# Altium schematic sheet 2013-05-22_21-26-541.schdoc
size 384 x 220 mm; SheetNumber: 1; SheetTotal: 1
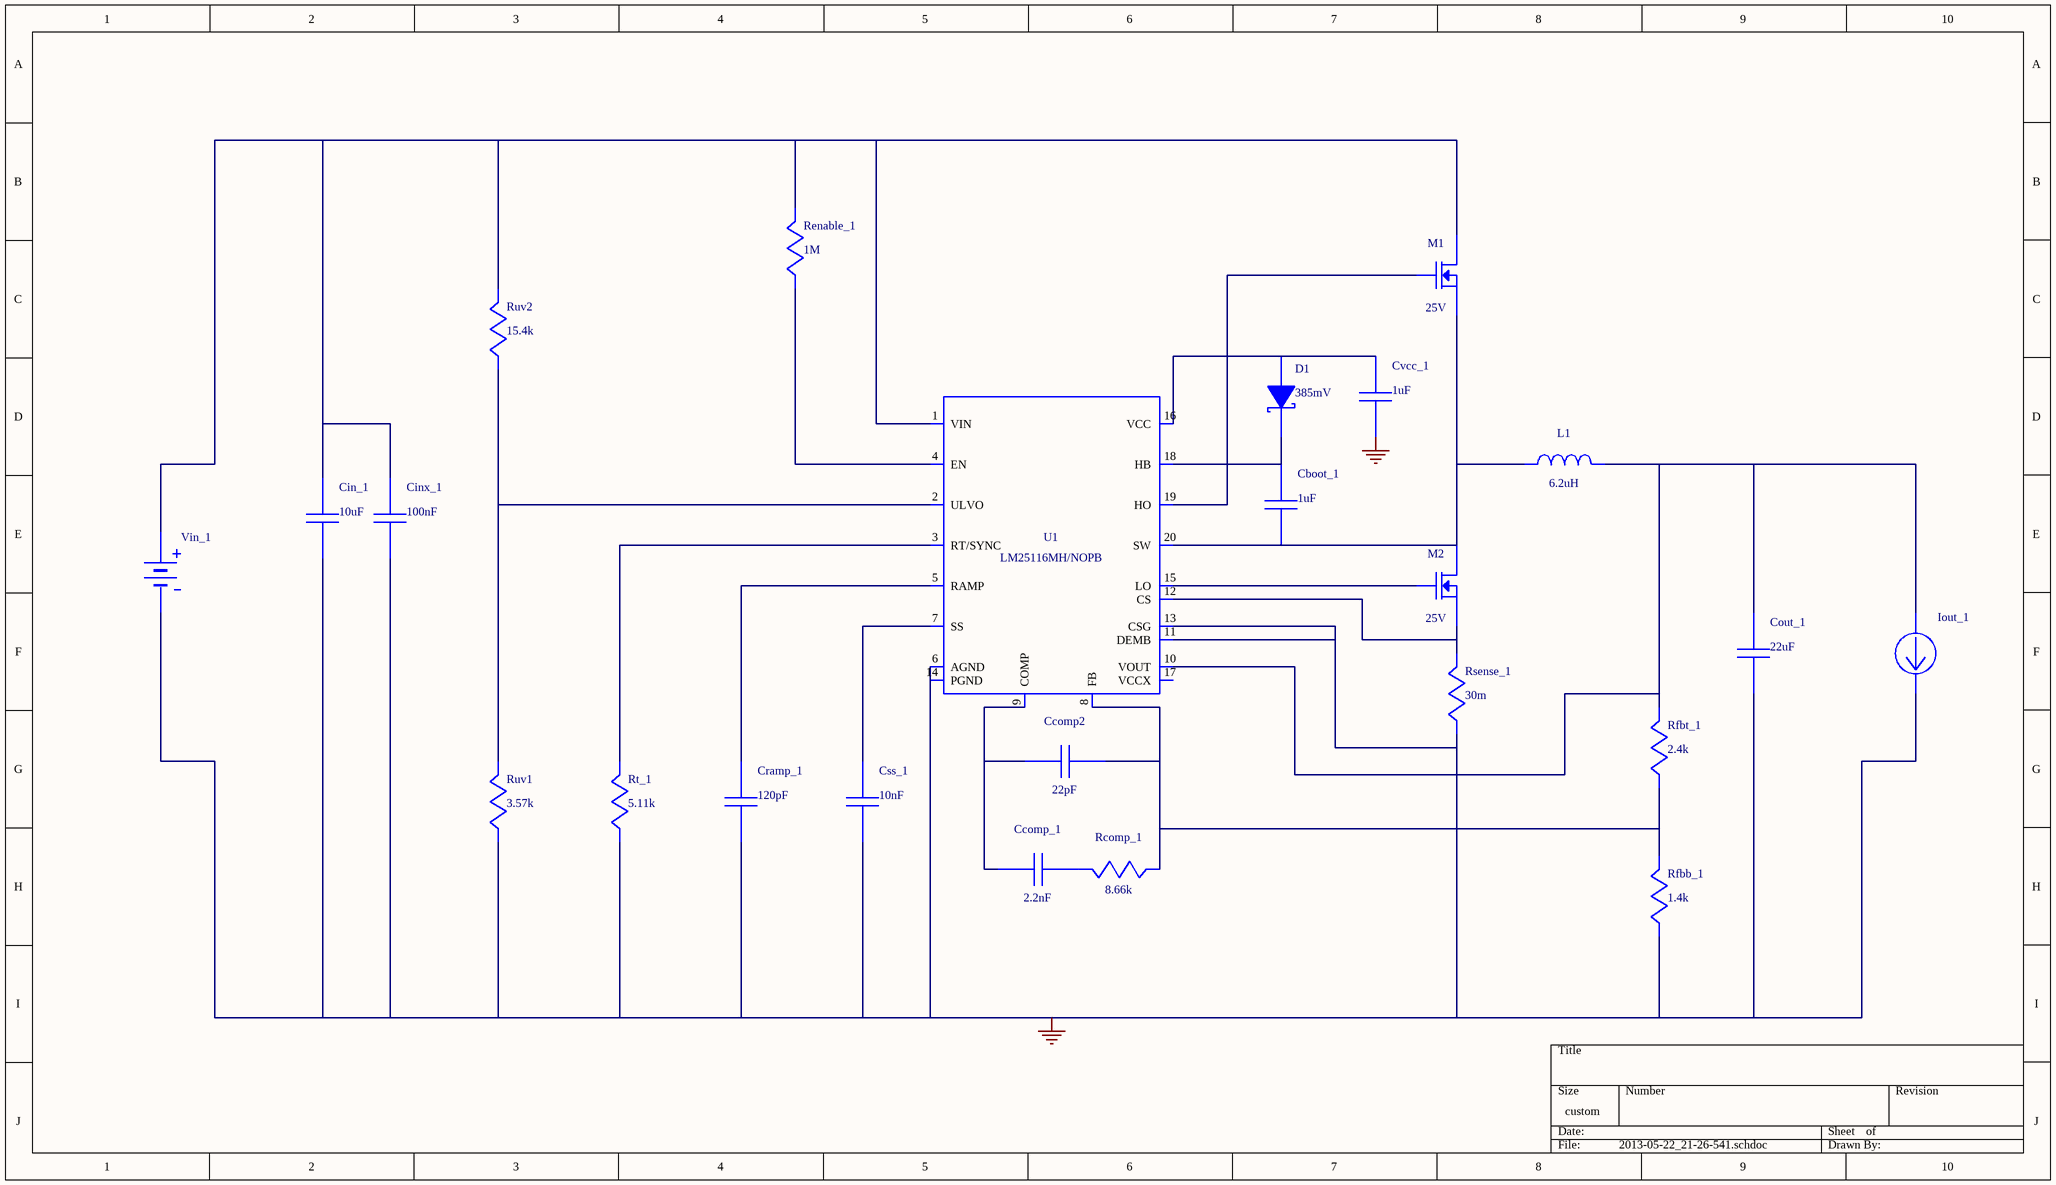
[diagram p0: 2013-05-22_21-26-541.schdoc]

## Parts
Cboot_1  value 1uF  (hidden comment: GRM155R61A105KE15D)
Ccomp2  value 22pF  (hidden comment: CC0805JRNP09BN220)
Ccomp_1  value 2.2nF  (hidden comment: CC0805KRX7R9BB222)
Cin_1  value 10uF  (hidden comment: C3225X5R1E106K)
Cinx_1  value 100nF  (hidden comment: 08053C104KAT2A)
Cout_1  value 22uF  (hidden comment: GRM21BR60J226ME39L)
Cramp_1  value 120pF  (hidden comment: CC0805JRNP09BN121)
Css_1  value 10nF  (hidden comment: GRM216R71H103KA01D)
Cvcc_1  value 1uF  (hidden comment: GRM155R61A105KE15D)
D1  value 385mV  (hidden comment: MBR0520LT1G)
Iout_1  WB_CURRENT_LOAD  (value not drawn)
L1  value 6.2uH  (hidden comment: SRU1038-6R2Y)
M1  value 25V  (hidden comment: CSD16301Q2)
M2  value 25V  (hidden comment: CSD16301Q2)
Rcomp_1  value 8.66k  (hidden comment: CRCW04028K66FKED)
Renable_1  value 1M  (hidden comment: CRCW04021M00FKED)
Rfbb_1  value 1.4k  (hidden comment: CRCW04021K40FKED)
Rfbt_1  value 2.4k  (hidden comment: RR1220P-242-D)
Rsense_1  value 30m  (hidden comment: CSR1206FK30L0)
Rt_1  value 5.11k  (hidden comment: CRCW04025K11FKED)
Ruv1  value 3.57k  (hidden comment: CRCW04023K57FKED)
Ruv2  value 15.4k  (hidden comment: CRCW040215K4FKED)
U1  LM25116MH/NOPB
Vin_1  WB_BATTERY  (value not drawn)

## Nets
0: Cin_1.2 Cinx_1.2 Cout_1.2 Cramp_1.2 Css_1.2 Cvcc_1.2 Iout_1.2(-) Rfbb_1.2 Rsense_1.2 Rt_1.2 Ruv1.2 U1.6(AGND) U1.11(DEMB) U1.13(CSG) U1.14(PGND) U1.21(EP) Vin_1.2(-)
NetCboot_1_1: Cboot_1.1 D1.1(K) U1.18(HB)
NetCboot_1_2: Cboot_1.2 L1.2 M1.4(Source) M1.7(Source) M2.1(Drain) M2.2(Drain) M2.5(Drain) M2.6(Drain) M2.8(Drain) U1.20(SW)
NetCcomp2_1: Ccomp2.1 Ccomp_1.1 U1.9(COMP)
NetCcomp2_2: Ccomp2.2 Rcomp_1.2 Rfbb_1.1 Rfbt_1.2 U1.8(FB)
NetCcomp_1_2: Ccomp_1.2 Rcomp_1.1
NetCin_1_1: Cin_1.1 Cinx_1.1 M1.1(Drain) M1.2(Drain) M1.5(Drain) M1.6(Drain) M1.8(Drain) Renable_1.1 Ruv2.1 U1.1(VIN) Vin_1.1(+)
NetCout_1_1: Cout_1.1 Iout_1.1(+) L1.1 Rfbt_1.1 U1.10(VOUT)
NetCramp_1_1: Cramp_1.1 U1.5(RAMP)
NetCss_1_1: Css_1.1 U1.7(SS)
NetCvcc_1_1: Cvcc_1.1 D1.2(A) U1.16(VCC)
NetM1_3: M1.3(Gate) U1.19(HO)
NetM2_3: M2.3(Gate) U1.15(LO)
NetM2_4: M2.4(Source) M2.7(Source) Rsense_1.1 U1.12(CS)
NetRenable_1_2: Renable_1.2 U1.4(EN)
NetRt_1_1: Rt_1.1 U1.3(RT/SYNC)
NetRuv1_1: Ruv1.1 Ruv2.2 U1.2(ULVO)

Not connected (* = marked no-connect by the designer): U1 17(VCCX)

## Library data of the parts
Cboot_1 Cvcc_1 = GRM155R61A105KE15D: GRM155R61A105KE1; Manufacturer Name: MuRata
Ccomp2 = CC0805JRNP09BN220: CC0805JRNP09BN22; Manufacturer Name: Yageo America
Ccomp_1 = CC0805KRX7R9BB222: CC0805KRX7R9BB22; Manufacturer Name: Yageo America
Cin_1 = C3225X5R1E106K: Manufacturer Name: TDK
Cinx_1 = 08053C104KAT2A: Manufacturer Name: AVX
Cout_1 = GRM21BR60J226ME39L: GRM21BR60J226ME3; Manufacturer Name: MuRata
Cramp_1 = CC0805JRNP09BN121: CC0805JRNP09BN12; Manufacturer Name: Yageo America
Css_1 = GRM216R71H103KA01D: GRM216R71H103KA0; Manufacturer Name: MuRata
D1 = MBR0520LT1G: Manufacturer Name: ON Semiconductor
Iout_1 = WB_CURRENT_LOAD: Value: UNLISTED
L1 = SRU1038-6R2Y: Manufacturer Name: Bourns
M1 M2 = CSD16301Q2: Manufacturer Name: Texas Instruments
Rcomp_1 = CRCW04028K66FKED: Manufacturer Name: Vishay-Dale
Renable_1 = CRCW04021M00FKED: Manufacturer Name: Vishay-Dale
Rfbb_1 = CRCW04021K40FKED: Manufacturer Name: Vishay-Dale
Rfbt_1 = RR1220P-242-D: Manufacturer Name: Susumu Co Ltd
Rsense_1 = CSR1206FK30L0: Manufacturer Name: Stackpole Electronics Inc
Rt_1 = CRCW04025K11FKED: Manufacturer Name: Vishay-Dale
Ruv1 = CRCW04023K57FKED: Manufacturer Name: Vishay-Dale
Ruv2 = CRCW040215K4FKED: Manufacturer Name: Vishay-Dale
U1 = LM25116MH/NOPB: Manufacturer Name: Texas Instruments; Value: UNLISTED
Vin_1 = WB_BATTERY: Value: UNLISTED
